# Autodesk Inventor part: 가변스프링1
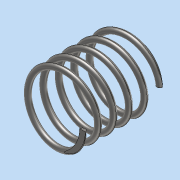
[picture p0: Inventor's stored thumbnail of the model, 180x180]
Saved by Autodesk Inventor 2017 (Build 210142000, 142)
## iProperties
Part Number: 가변스프링1
Material: 강철, 연강
Document SubType Name: Modeling
Designer: MRC
Density: 7.85 g/cm^3
Appearance: 반연마
Mass: 8.38973 g
Surface Area: 21.6696 cm^2
Volume: 1.06876 cm^3
Author: MRC
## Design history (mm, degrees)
sketch "스케치1"
  geometry: L1 (0, 0)-(0, -27.345); L2 (0, 0)-(11, 0); L3 (0, -27.345)-(11.069, -27.345); C1 r 1 at (11, 0)
  constraints: 6 end point, 2 horizontal, 1 centre point, 1 coincident, 1 vertical
  dimensions: "d1" = 22 diameter of L2.end L1; "d2" = 2 diameter of C1; "d4" = 27.3455 distance of L1.start L1.end (derived)
feature "코일1" sketch "스케치1" pitch "d5" = 10; turns "d7" = 5; dims "d6" = 27.3455 (= d4), "d8" = 0, angle "d9" = 90 deg, angle "d10" = 90 deg, "d11" = 0, "d12" = 0
sketch "스케치2"
  geometry: L1 (0, 13.296)-(-27.345, 13.296); L2 (-27.345, 13.296)-(-27.345, -12.495); L3 (-27.345, -12.495)-(0, -12.495); L4 (0, -12.495)-(0, 13.296); 1 further point
  constraints: 8 end point, 2 parallel, 1 horizontal, 1 perpendicular, 1 point on line
  dimensions: "d17" = 27.3455 distance of L2.end L3.end (= d4)
extrude "돌출1" sketch "스케치2" stored distance "d15" = 30; taper "d16" = 0 deg
node "솔리드1"
